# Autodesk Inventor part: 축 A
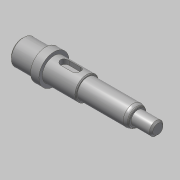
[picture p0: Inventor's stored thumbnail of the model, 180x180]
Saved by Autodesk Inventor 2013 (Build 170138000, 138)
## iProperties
Created: 2020-04
Part Number: 축 A
Material: 강철, 연강
Document SubType Name: Modeling
Designer: mduedu
Density: 1 g/cm^3
Author: mduedu
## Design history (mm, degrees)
sketch "스케치1"
  geometry: L1 (0, 0)-(14, 0); L2 (14, 0)-(14, 7.5); L3 (14, 7.5)-(0, 7.5); L4 (0, 7.5)-(0, 0); L5 (14, 0)-(19, 0); L6 (19, 0)-(19, 9); L7 (19, 9)-(14, 9); L8 (14, 9)-(14, 0); L9 (19, 0)-(39, 0); L10 (39, 0)-(39, 7); L11 (39, 7)-(19, 7); L12 (19, 7)-(19, 0); L13 (39, 0)-(69, 0); L14 (69, 0)-(69, 6); L15 (69, 6)-(39, 6); L16 (39, 6)-(39, 0); L17 (69, 0)-(81, 0); L18 (81, 0)-(81, 4); L19 (81, 4)-(69, 4); L20 (69, 4)-(69, 0)
  constraints: 40 end point, 10 parallel, 5 horizontal, 5 perpendicular
  dimensions: "d0" = 81 distance between parallel lines of L18 L4; "d2" = 14 distance of L2.end L3.end; "d3" = 5 distance of L6.end L7.end; "d4" = 12 distance of L18.end L19.end; "d5" = 8 diameter of L19 L17; "d6" = 12 diameter of L15 L13; "d7" = 14 diameter of L11 L9; "d8" = 15 diameter of L3 L1; "d9" = 18 diameter of L7 L5; "d10" = 42 distance between parallel lines of L10 L18
revolve "회전1" sketch "스케치1" stored, may be unused: angle "d11" = 90 deg
sketch "스케치2"
  geometry: L1 (0, -7.5)-(0, 7.5) reference; L2 (0, 7.5)-(14, 7.5) reference; L3 (14, 7.5)-(14, 9) reference; L4 (14, 9)-(19, 9) reference; L5 (19, 9)-(19, 7) reference; L6 (19, 7)-(39, 7) reference; L7 (39, 7)-(39, 6) reference; L8 (39, 6)-(69, 6) reference; L9 (69, 6)-(69, 4) reference; L10 (69, 4)-(81, 4) reference; L11 (81, 4)-(81, -4) reference; L12 (81, -4)-(69, -4) reference; L13 (69, -4)-(69, -6) reference; L14 (69, -6)-(39, -6) reference; L15 (39, -6)-(39, -7) reference; L16 (39, -7)-(19, -7) reference; L17 (19, -7)-(19, -9) reference; L18 (19, -9)-(14, -9) reference; L19 (14, -9)-(14, -7.5) reference; L20 (14, -7.5)-(0, -7.5) reference; L21 (81, -4)-(73, -4); L22 (73, -4)-(73, -2.8); L23 (73, -2.8)-(81, -2.8); L24 (81, -2.8)-(81, -4); 1 further point
  constraints: 8 end point, 2 parallel, 1 horizontal, 1 perpendicular
  dimensions: "d12" = 8 distance of L22.end L23.end; "d13" = 1.2 distance of L21.end L22.end
extrude "돌출1" cut sketch "스케치2" stored distance "d14" = 2; taper "d15" = 0 deg
fillet "모깎기1" dims "d16" = 1
sketch "스케치3"
  geometry: L1 (0, -7.5)-(0, 7.5) reference; L2 (0, 7.5)-(14, 7.5) reference; L3 (14, 7.5)-(14, 9) reference; L4 (14, 9)-(19, 9) reference; L5 (19, 9)-(19, 7) reference; L6 (19, 7)-(39, 7) reference; L7 (39, 7)-(39, 6) reference; L8 (39, 6)-(69, 6) reference; L9 (69, 6)-(69, 4) reference; L10 (69, 4)-(81, 4) reference; L11 (81, 4)-(81, -2.8) reference; L12 (81, -2.8)-(73, -2.8) reference; L13 (73, -2.8)-(73, -4) reference; L14 (73, -4)-(69, -4) reference; L15 (69, -4)-(69, -6) reference; L16 (69, -6)-(39, -6) reference; L17 (39, -6)-(39, -7) reference; L18 (39, -7)-(19, -7) reference; L19 (19, -7)-(19, -9) reference; L20 (19, -9)-(14, -9) reference; L21 (14, -9)-(14, -7.5) reference; L22 (14, -7.5)-(0, -7.5) reference; L23 (23, 7)-(35, 7); L24 (35, 7)-(35, 4); L25 (35, 4)-(23, 4); L26 (23, 4)-(23, 7); 1 further point
  constraints: 8 end point, 2 parallel, 1 horizontal, 1 perpendicular, 1 point on line
  dimensions: "d17" = 12 distance of L24.end L25.end; "d18" = 3 distance of L23.end L24.end; "d19" = 4 distance from line of L26 L4.end
extrude "돌출2" cut sketch "스케치3" stored distance "d20" = 5; taper "d21" = 0 deg
fillet "모깎기2" dims "d22" = 2.5
chamfer "모따기1" distance "d23" = 1; stored, may be unused: second distance "d24" = 2, angle "d25" = 45 deg
chamfer "모따기2" distance "d26" = 0.5; stored, may be unused: second distance "d27" = 2, angle "d28" = 45 deg
fillet "모깎기3" dims "d29" = 0.3
chamfer "모따기3" distance "d30" = 1.56; stored, may be unused: second distance "d31" = 2, angle "d32" = 30 deg
fillet "모깎기4" dims "d33" = 4, "d34" = 0.5
node "솔리드1"
node "절단 모서리 투영1"
node "절단 모서리 투영2"
